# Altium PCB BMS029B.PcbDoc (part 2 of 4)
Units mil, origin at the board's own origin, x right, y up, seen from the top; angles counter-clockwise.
Board outline 4950 x 4000 mil, 4 copper layers (Layer 1 - Top Layer, Layer 2 - GND, Layer 3 - Signal, Layer 4 - Bottom Layer), stack 61.4 mil thick; 370 components, 202 nets, 969 pads, 408 vias.
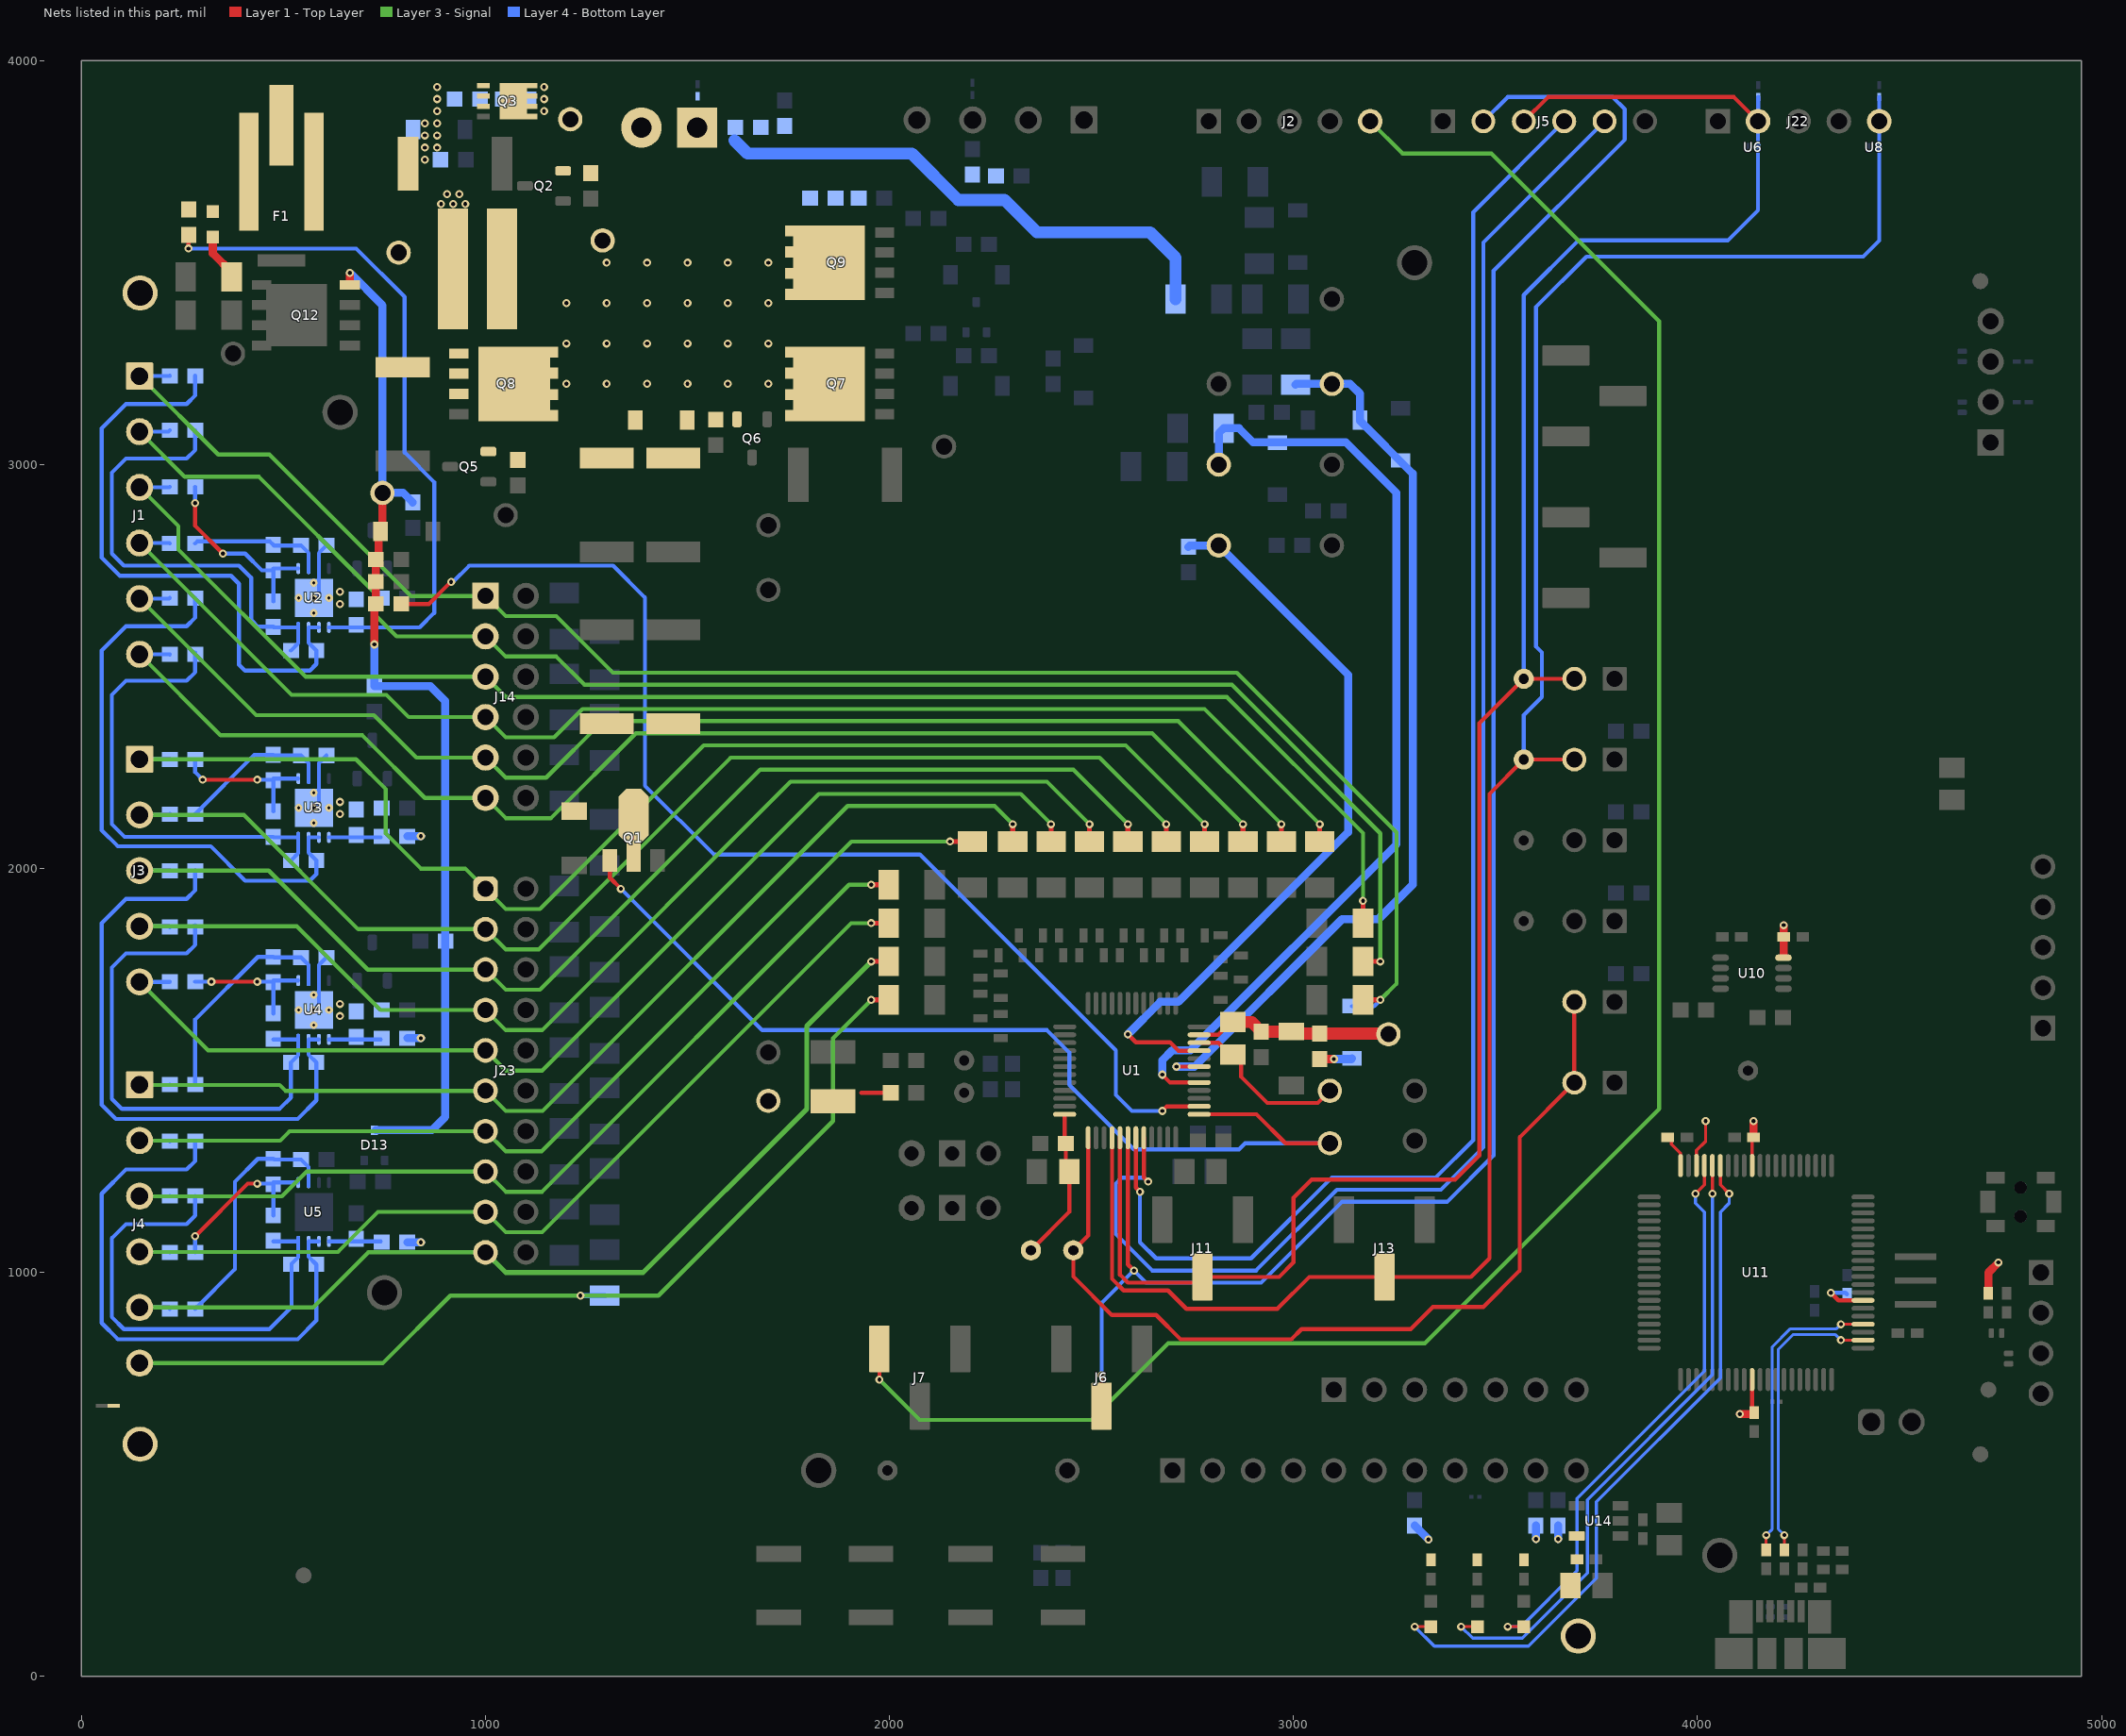
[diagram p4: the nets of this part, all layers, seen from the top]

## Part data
C1 C71: library part CMP-0008710-2, "CAP, CERM, 1 uF, 100 V, +/- 10%, X7R, 1206", Cap_Case=1206_180, Manufacturer=TDK, Supplier Part Number 1=445-4467-1-ND, TempCo=X7R, Tolerance_%=10%, Value1="0.004575 ohm", Value2=100V, ValueDisplayed=1uF
C2: library part CMP-0007130-4, "CAP, CERM, 100 pF, 100 V, +/- 5%, C0G/NP0, AEC-Q200 Grade 1, 0603", Cap_Case=0603, Manufacturer=MuRata, Supplier Part Number 1=490-4771-1-ND, TempCo=C0G/NP0, Tolerance_%=5%, Value1=Unknown, Value2=100V, ValueDisplayed=100pF
C3: library part CMP-0008010-2, "CAP, CERM, 0.47 uF, 25 V, +/- 10%, X7R, AEC-Q200 Grade 1, 0805", Cap_Case=0805, Manufacturer=MuRata, Supplier Part Number 1=490-8044-1-ND, TempCo=X7R, Tolerance_%=10%, Value1=Unknown, Value2=25V, ValueDisplayed=0.47uF
C4 C5 C6 C7 C8 C9 C10 C11 C14 C16 C17 C18 C19 C21 C22 C23 C24: library part CMP-0007047-4, "CAP, CERM, 0.22 uF, 50 V, +/- 10%, X7R, 0603", Cap_Case=0603, Manufacturer=TDK, Supplier Part Number 1=445-7408-1-ND, TempCo=X7R, Tolerance_%=10%, Value1="0.021699 ohm", Value2=50V, ValueDisplayed=0.22uF
C12 C15: library part CMP-0008000-2, "CAP, CERM, 1 uF, 16 V, +/- 10%, X7R, 0805", Cap_Case=0805, Manufacturer="Taiyo Yuden", Supplier Part Number 1=587-1283-1-ND, TempCo=X7R, Tolerance_%=10%, Value1=Unknown, Value2=16V, ValueDisplayed=1uF
C13: library part CMP-0006900-4, "CAP, CERM, 0.022 uF, 16 V, +/- 10%, X7R, 0603", Cap_Case=0603, Manufacturer=Kemet, Supplier Part Number 1=399-1093-1-ND, TempCo=X7R, Tolerance_%=10%, Value1=Unknown, Value2=16V, ValueDisplayed=0.022uF
C20 C26: library part CMP-0006828-4, "CAP, CERM, 0.01 uF, 16 V, +/- 10%, X7R, 0603", Cap_Case=0603, Manufacturer="Wurth Elektronik", Supplier Part Number 1=732-7959-1-ND, TempCo=X7R, Tolerance_%=10%, Value1=Unknown, Value2=16V, ValueDisplayed=0.01uF
C25: library part CMP-0008001-2, "CAP, CERM, 2.2 uF, 16 V, +/- 10%, X7R, 0805", Cap_Case=0805, Manufacturer="Taiyo Yuden", Supplier Part Number 1=587-1431-1-ND, TempCo=X7R, Tolerance_%=10%, Value1=Unknown, Value2=16V, ValueDisplayed=2.2uF
C27: library part CMP-0006841-4, "CAP, CERM, 100 pF, 50 V, +/- 5%, C0G/NP0, 0603", Cap_Case=0603, Manufacturer=Kemet, Supplier Part Number 1=399-1061-1-ND, TempCo=C0G/NP0, Tolerance_%=5%, Value1=Unknown, Value2=50V, ValueDisplayed=100pF
C28 C31 C32 C33 C35 C39 C40 C41 C43 C44 C46 C47 C48 C49 C50 C51 C52 C53 C54 C55 C56 C57: library part CMP-0006837-4, "CAP, CERM, 0.1 uF, 50 V, +/- 10%, X7R, 0603", Cap_Case=0603, Manufacturer="Wurth Elektronik", TempCo=X7R, Tolerance_%=10%, Value1=Unknown, Value2=50V, ValueDisplayed=0.1uF
C29 C30 C34 C36 C37 C38 C42 C45: library part CMP-0064935-4, "CAP, CERM, 0.1 uF, 100 V,+/- 10%, X7R, AEC-Q200 Grade 1, 0603", Cap_Case=0603, Manufacturer=MuRata, Supplier Part Number 1=490-13420-1-ND, TempCo=X7R, Tolerance_%=10%, Value1=Unknown, Value2=100V, ValueDisplayed=0.1uF
C58 C59 C60 C62 C65 C66 C68: library part CMP-0006228-2, "CAP, CERM, 0.1 uF, 16 V, +/- 10%, X7R, 0402", Cap_Case=0402, Manufacturer="Wurth Elektronik", Supplier Part Number 1=732-7532-1-ND, TempCo=X7R, Tolerance_%=10%, Value1=Unknown, Value2=16V, ValueDisplayed=0.1uF
C61 C67 C69: library part CMP-0006199-2, "CAP, CERM, 0.47 uF, 6.3 V, +/- 10%, X5R, 0402", Cap_Case=0402, Manufacturer=AVX, PartNumber=04026D474KAT2A, Supplier Part Number 1=478-6196-1-ND, TempCo=X5R, Tolerance_%=10%, Value1=Unknown, Value2=6.3V, ValueDisplayed=0.47uF
C63 C64: library part CMP-0085538-1, "CAP, CERM, 10 µF, 16 V,+/- 10%, X5R, 0805", Cap_Case=0805, Manufacturer="Samsung Electro-Mechanics", TempCo=X5R, Tolerance_%=10%, Value2=16V, ValueDisplayed=10µF
C70: library part CMP-0006224-2, "CAP, CERM, 2200 pF, 10 V, +/- 10%, X7R, 0402", Cap_Case=0402, Manufacturer="Wurth Elektronik", Supplier Part Number 1=732-7503-1-ND, TempCo=X7R, Tolerance_%=10%, Value1=Unknown, Value2=10V, ValueDisplayed=2200pF
D1 D2 D9 D10 D11 D12: library part CMP-0028450-2, "Diode, Schottky, 100 V, 0.15 A, SOD-123", Manufacturer="Diodes Inc.", Value1=0.15A, Value2=0.6V
D3: library part CMP-0002947-3, "LED, Red, SMD", Color=Red, Manufacturer="Wurth Elektronik", Power_TotalModule=72mW, Value1=0.072W, Value2=2V
D4 D5 D6: library part CMP-0005754-4, "Diode, Zener, 16 V, 500 mW, SOD-123", Manufacturer="Diodes Inc.", Power_W=500mW, Value1=0.5W
D7: library part CMP-0029001-2, "Diode, Ultrafast, 100 V, 0.15 A, SOD-123", Manufacturer="Diodes Inc.", Value1=0.15A, Value2=1.25V
D8: library part CMP-0005740-3, "Diode, Zener, 10 V, 500 mW, SOD-123", Manufacturer="ON Semiconductor", Power_W=500mW, Value1=0.5W
D13: library part CMP-0028438-2, "Diode, Schottky, 40 V, 0.2 A, SOT-323", Manufacturer="Diodes Inc.", Value1=0.2A, Value2=0.9V
D14 D15 D16: library part CMP-0002894-2, "LED, Green, SMD", Color=green, Manufacturer="Wurth Elektronik", Value1=W, Value2=2V
E1 E2 E3 E4 E5 E6: library part CMP-0079939-1
F1: library part CMP-0078325-2, "Fuse, 30 A, 62 VDC, SMD", Irating_A=30A, Manufacturer="Dexerials Corporation"
FID1 FID2 FID3 FID4 FID5 FID6: library part CMP-0077181-1, "Fiducial mark.  There is nothing to buy or mount.", Manufacturer=N/A
H1 H2 H3 H4: library part CMP-0003620-1, "Bumpon, Hemisphere, 0.44 X 0.20, Clear", Manufacturer=3M, Supplier Part Number 1=SJ5303-7-ND
J1 J4: library part CMP-0087050-1, "TERM BLOCK 3.5MM VERT 6POS PCB", Current_A=10A, Manufacturer="On Shore Technology", Voltage_V=300V
J2 J22 J28: library part CMP-0054597-1, "Header, 2.54mm, 5x1, Tin, TH", Color=Black, Current_A=3A, Manufacturer="Sullins Connector Solutions", Supplier Part Number 1=S1012E-05-ND, Voltage_V=1.8kV
J3: library part CMP-0087049-1, "TERM BLOCK 3.5MM VERT 5POS PCB", Current_A=10A, Manufacturer="On Shore Technology", Voltage_V=300V
J5: library part CMP-0054567-1, "Header, 100mil, 6x1, Tin, TH", Manufacturer="Sullins Connector Solutions", Supplier Part Number 1=S1012E-06-ND
J6 J7 J11 J13 J16 J19: library part CMP-0075388-1, "Header, 2.54mm, 3x1, Gold, SMT", Color=Black, Current_A=3A, Manufacturer=Molex, Supplier Part Number 1=0878980304-ND, Voltage_V=250V
J8: library part CMP-0074913-1, "Terminal Block, 3.5mm Pitch, 2x1, TH", Color=Grey, Current_A=6A, Manufacturer="On-Shore Technology", Supplier Part Number 1=ED1514-ND, Voltage_V=150V
J9: library part CMP-0087048-1, "TERM BLOCK 3.5MM VERT 4POS PCB", Current_A=10A, Manufacturer="On Shore Technology", Voltage_V=300V
J10 J12 J15 J18 J20 J21: library part CMP-0002337-1, "Header, 100mil, 2x1, Tin, TH", Color=Black, Current_A=3A, Manufacturer="Sullins Connector Solutions", Supplier Part Number 1=S1012E-02-ND, Voltage_V=1.8kV
J14: library part CMP-0054551-2, "Header, 100mil, 6x2, Tin, TH", Color=Black, Current_A=3A, Manufacturer="Sullins Connector Solutions", Supplier Part Number 1=S2012E-06-ND, Voltage_V=1.8kV
J17: library part CMP-0055187-1, "Header (friction lock), 100mil, 4x1, R/A, TH", Manufacturer=Molex, Supplier Part Number 1=WM4302-ND
J23: library part CMP-0054623-2, "Header, 2.54mm, 10x2, Tin, TH", Color=Black, Current_A=3A, Manufacturer="Sullins Connector Solutions", Supplier Part Number 1=S2012E-10-ND
J24: library part CMP-0054584-1, "Header, 2.54 mm, 7x1, Gold, TH", Color=Black, Current_A=3A, Manufacturer="Sullins Connector Solutions", Supplier Part Number 1=S1011E-07-ND, Voltage_V=1.8kV
J25: library part CMP-0054585-1, "Header, 2.54 mm, 11x1, Gold, TH", Color=Black, Current_A=3A, Manufacturer="Sullins Connector Solutions", Supplier Part Number 1=S1011E-11-ND, Voltage_V=1.8kV
J26: library part CMP-0055304-1, "Receptacle, Micro-USB Type B, 0.65 mm, 5x1, R/A, Bottom Mount SMT", Manufacturer=Molex, PartNumber=47346-1001, Supplier Part Number 1=06X9936
J27: library part CMP-0054794-2, "Header, 2.54 mm, 2x1, Gold, TH", Color=Black, Manufacturer="Wurth Elektronik", Supplier Part Number 1=732-5315-ND
J29: library part CMP-0055331-1, "Header, 2.54mm, 4x1, Tin, TH", Color=Black, Current_A=4A, Manufacturer=Molex, Supplier Part Number 1=WM50016-04-ND, Voltage_V=250V
LOGO4 LOGO5: library part CMP-0074835-1, "IEC 61010-1 High Voltage Warning"
Logo8: library part CMP-0074847-1, "FCC_disclaimer"
Logo9: library part CMP-0074769-1
Logo10: library part CMP-0074836-1, "IEC 61010-1 Caution Warning"
NT1 NT2 NT3 NT4 NT5: library part CMP-0078142-3, "Single point connection between nets.", Manufacturer=N/A
Q1: library part CMP-0000510-2, "Transistor, NPN, 150 V, 1 A, AEC-Q101, SOT-89", Manufacturer="Diodes Inc.", Supplier Part Number 1=FCX495CT-ND, Value1="1 A", Value2=300
Q2 Q5 Q6: library part CMP-0000093-3, "MOSFET, P-CH, -150 V, -0.53 A, SOT-23", Alternate Manufacturer=None, Manufacturer=Vishay-Siliconix, Value2="7.7 nC"
Q3: library part CMP-0001051-2, "MOSFET, N-CH, 150 V, 13 A, PG-TSDSON-8", Alternate Manufacturer=None, Manufacturer="Infineon Technologies", Supplier Part Number 1="BSZ900N15NS3 GCT-ND", Value2="5 nC"
Q4 Q11 Q13: library part CMP-0000333-2, "Transistor, PNP, 150 V, 0.5 A, SOT-23", Manufacturer="ON Semiconductor", Supplier Part Number 1=MMBT5401LT1GOSCT-ND, Value1="0.5 A", Value2=240
Q7 Q8 Q9: library part CMP-0067566-1, "MOSFET, N-CH, 150 V, 56 A, PG-TDSON-8", Alternate Manufacturer=None, Manufacturer="Infineon Technologies", Supplier Part Number 1=BSC160N15NS5ATMA1-ND, Value1="? ohm", Value2="19 nC"
Q10: library part CMP-0000774-1, "MOSFET, N-CH, 60 V, 0.31 A, SOT-323", Alternate Manufacturer=None, Manufacturer="Fairchild Semiconductor", PartNumber=2N7002KW, Supplier Part Number 1=2N7002KWCT-ND, Value1=1
Q12: library part CMP-0001069-3, "MOSFET, N-CH, 150 V, 3 A, PowerPAK SO-8", Alternate Manufacturer=None, Manufacturer=Vishay-Siliconix, Supplier Part Number 1=SI7898DP-T1-E3CT-ND, Value1=0.07, Value2="17 nC"
R1 R27 R28 R31 R41 R67 R81: library part CMP-0025700-4, "RES, 100, 5%, 0.1 W, AEC-Q200 Grade 0, 0603", Manufacturer=Vishay-Dale, PartNumber=CRCW0603100RJNEA, Power_W=100mW, Supplier Part Number 1=541-100GCT-ND, TempCo="200 ppm/C", Tolerance_%=5%, Value2=0.1W, Value_Code=100R, ValueDisplayed=100
R2 R3 R4 R7 R8 R11 R12 R13 R14 R16 R17 R18 R19 R21 R22 R23 R24: library part CMP-0016781-3, "RES, 20.0, 1%, 0.25 W, AEC-Q200 Grade 0, 1206", Manufacturer=Vishay-Dale, Power_W=250mW, Supplier Part Number 1=541-20.0FCT-ND, TempCo="100 ppm/C", Tolerance_%=1%, Value2=0.25W, Value_Code=20R0, ValueDisplayed=20.0
R5 R6 R9 R10: library part CMP-0015916-3, "RES, 220, 5%, 1 W, AEC-Q200 Grade 0, 2512", Manufacturer=Vishay-Dale, Power_W=1W, Supplier Part Number 1=541-220XCT-ND, TempCo="200 ppm/C", Tolerance_%=5%, Value_Code=220R, ValueDisplayed=220
R15 R56 R112 R113: library part CMP-0025697-4, "RES, 0, 5%, 0.1 W, AEC-Q200 Grade 0, 0603", Manufacturer=Vishay-Dale, Power_W=100mW, Supplier Part Number 1=541-0.0GCT-ND, TempCo="200 ppm/C", Tolerance_%=5%, Value2=0.1W, Value_Code=0000, ValueDisplayed=0
R20 R25 R29 R89 R92 R94 R97 R99 R109 R110 R111: library part CMP-0025701-4, "RES, 10 k, 5%, 0.1 W, AEC-Q200 Grade 0, 0603", Manufacturer=Vishay-Dale, Power_W=100mW, Supplier Part Number 1=541-10KGCT-ND, TempCo="200 ppm/C", Tolerance_%=5%, Value2=0.1W, Value_Code=10k0, ValueDisplayed=10k
R26 R91: library part CMP-0025698-4, "RES, 100 k, 5%, 0.1 W, AEC-Q200 Grade 0, 0603", Manufacturer=Vishay-Dale, Power_W=100mW, Supplier Part Number 1=541-100KGCT-ND, TempCo="200 ppm/C", Tolerance_%=5%, Value2=0.1W, Value_Code=100k
R30: library part CMP-0015200-2, "RES, 0.001, 1%, 1 W, 1210", Manufacturer=Rohm, PartNumber=PMR25HZPFV1L00, Power_W=1W, Supplier Part Number 1=RHM.001APCT-ND, TempCo="100 ppm/C", Tolerance_%=1%, Value_Code=1L000, ValueDisplayed=0.001
R32 R34 R36 R37 R47 R49 R53 R54 R69 R72 R75 R78 R83 R84 R85 R86: library part CMP-0025729-4, "RES, 1.0 k, 5%, 0.1 W, AEC-Q200 Grade 0, 0603", Manufacturer=Vishay-Dale, PartNumber=CRCW06031K00JNEA, Power_W=100mW, Supplier Part Number 1=541-1.0KGCT-ND, TempCo="200 ppm/C", Tolerance_%=5%, Value2=0.1W, Value_Code=1k00, ValueDisplayed=1.0k
R33 R39 R40: library part CMP-0015972-3, "RES, 4.7 k, 5%, 1 W, AEC-Q200 Grade 0, 2512", Manufacturer=Vishay-Dale, Power_W=1W, Supplier Part Number 1=541-4.7KXCT-ND, TempCo="200 ppm/C", Tolerance_%=5%, Value_Code=4k70, ValueDisplayed=4.7k
R35 R42 R43 R50 R51 R52: library part CMP-0025702-4, "RES, 10 M, 5%, 0.1 W, AEC-Q200 Grade 0, 0603", Manufacturer=Vishay-Dale, PartNumber=CRCW060310M0JNEA, Power_W=100mW, Supplier Part Number 1=541-10MGCT-ND, TempCo="200 ppm/C", Tolerance_%=5%, Value2=0.1W, Value_Code=10M0, ValueDisplayed=10M
R38 R58 R79: library part CMP-0025753-4, "RES, 20 k, 5%, 0.1 W, AEC-Q200 Grade 0, 0603", Manufacturer=Vishay-Dale, Power_W=100mW, Supplier Part Number 1=541-20KGCT-ND, TempCo="200 ppm/C", Tolerance_%=5%, Value2=0.1W, Value_Code=20k0, ValueDisplayed=20k
R44: library part CMP-0023326-5, "RES, 95.3 k, 1%, 0.1 W, 0603", Manufacturer=Yageo, Power_W=100mW, Supplier Part Number 1=311-95.3KHRCT-ND, TempCo="100 ppm/C", Tolerance_%=1%, Value2=0.1W, Value_Code=95k3, ValueDisplayed=95.3k
R45 R48: library part CMP-0018728-3, "RES, 7.5 k, 5%, 0.25 W, AEC-Q200 Grade 0, 1206", Manufacturer=Vishay-Dale, Power_W=250mW, Supplier Part Number 1=541-7.5KECT-ND, TempCo="200 ppm/C", Tolerance_%=5%, Value2=0.25W, Value_Code=7k50, ValueDisplayed=7.5k
R46: library part CMP-0015368-2, "RES, 0, 5%, 2 W, 2512 WIDE", Manufacturer="Vishay Draloric", PartNumber=RCL12250000Z0EG, Power_W=2W, Supplier Part Number 1=RCL0.0ECT-ND, TempCo=ppm/C, Tolerance_%=5%, Value_Code=0000, ValueDisplayed=0
R55: library part CMP-0025825-4, "RES, 51, 5%, 0.1 W, AEC-Q200 Grade 0, 0603", Manufacturer=Vishay-Dale, Power_W=100mW, Supplier Part Number 1=541-51GCT-ND, TempCo="200 ppm/C", Tolerance_%=5%, Value2=0.1W, Value_Code=51R0, ValueDisplayed=51
R57: library part CMP-0025701-4, "RES, 10 k, 5%, 0.1 W, AEC-Q200 Grade 0, 0603", Manufacturer=Vishay-Dale, PartNumber=CRCW060310K0JNEA, Power_W=100mW, Supplier Part Number 1=541-10KGCT-ND, TempCo="200 ppm/C", Tolerance_%=5%, Value2=0.1W, Value_Code=10k0, ValueDisplayed=10k
R59 R82: library part CMP-0025830-4, "RES, 5.1 k, 5%, 0.1 W, AEC-Q200 Grade 0, 0603", Manufacturer=Vishay-Dale, PartNumber=CRCW06035K10JNEA, Power_W=100mW, Supplier Part Number 1=541-5.1KGCT-ND, TempCo="200 ppm/C", Tolerance_%=5%, Value2=0.1W, Value_Code=5k10, ValueDisplayed=5.1k
R60: library part CMP-0025935-5, "RES, 62 k, 5%, 0.1 W, 0603", Manufacturer=Yageo, Power_W=100mW, Supplier Part Number 1=311-62KGRCT-ND, TempCo="100 ppm/C", Tolerance_%=5%, Value2=0.1W, Value_Code=62k0, ValueDisplayed=62k
R61 R62 R63: library part CMP-0025830-4, "RES, 5.1 k, 5%, 0.1 W, AEC-Q200 Grade 0, 0603", Manufacturer=Vishay-Dale, Power_W=100mW, Supplier Part Number 1=541-5.1KGCT-ND, TempCo="200 ppm/C", Tolerance_%=5%, Value2=0.1W, Value_Code=5k10, ValueDisplayed=5.1k
R64 R68 R70 R71 R73 R74 R76 R77: library part CMP-0018703-3, "RES, 5.1 k, 5%, 0.25 W, AEC-Q200 Grade 0, 1206", Manufacturer=Vishay-Dale, Power_W=250mW, Supplier Part Number 1=541-5.1KECT-ND, TempCo="200 ppm/C", Tolerance_%=5%, Value2=0.25W, Value_Code=5k10, ValueDisplayed=5.1k
R65: library part CMP-0025855-4, "RES, 7.5 k, 5%, 0.1 W, AEC-Q200 Grade 0, 0603", Manufacturer=Vishay-Dale, Power_W=100mW, Supplier Part Number 1=541-7.5KGCT-ND, TempCo="200 ppm/C", Tolerance_%=5%, Value2=0.1W, Value_Code=7k50, ValueDisplayed=7.5k
R66: library part CMP-0025753-4, "RES, 20 k, 5%, 0.1 W, AEC-Q200 Grade 0, 0603", Manufacturer=Vishay-Dale, PartNumber=CRCW060320K0JNEA, Power_W=100mW, Supplier Part Number 1=541-20KGCT-ND, TempCo="200 ppm/C", Tolerance_%=5%, Value2=0.1W, Value_Code=20k0, ValueDisplayed=20k
R80: library part CMP-0025766-4, "RES, 27 k, 5%, 0.1 W, AEC-Q200 Grade 0, 0603", Manufacturer=Vishay-Dale, Power_W=100mW, Supplier Part Number 1=541-27KGCT-ND, TempCo="200 ppm/C", Tolerance_%=5%, Value2=0.1W, Value_Code=27k0, ValueDisplayed=27k
R87 R88 R90 R93 R95 R96 R98 R100 R101 R102 R103 R104 R105 R106 R107 R108: library part CMP-0016776-3, "RES, 200, 1%, 0.25 W, AEC-Q200 Grade 0, 1206", Manufacturer=Vishay-Dale, Power_W=250mW, Supplier Part Number 1=541-200FCT-ND, TempCo="100 ppm/C", Tolerance_%=1%, Value2=0.25W, Value_Code=200R, ValueDisplayed=200
R114 R115: library part CMP-0026908-3, "RES, 33, 5%, 0.063 W, AEC-Q200 Grade 0, 0402", Manufacturer=Vishay-Dale, PartNumber=CRCW040233R0JNED, Power_W=63mW, Supplier Part Number 1=541-33JCT-ND, TempCo="200 ppm/C", Tolerance_%=5%, Value2=0.063W, Value_Code=33R0, ValueDisplayed=33
R116: library part CMP-0026889-5, "RES, 2.0 k, 5%, 0.063 W, AEC-Q200 Grade 0, 0402", Manufacturer=Vishay-Dale, PartNumber=CRCW04022K00JNED, Power_W=63mW, Supplier Part Number 1=541-2.0KJCT-ND, TempCo="200 ppm/C", Tolerance_%=5%, Value2=0.063W, Value_Code=2k00, ValueDisplayed=2.0k
R117 R123: library part CMP-0026825-5, "RES, 10 k, 5%, 0.063 W, AEC-Q200 Grade 0, 0402", Manufacturer=Vishay-Dale, PartNumber=CRCW040210K0JNED, Power_W=63mW, Supplier Part Number 1=541-10KJCT-ND, TempCo="200 ppm/C", Tolerance_%=5%, Value2=0.063W, Value_Code=10k0, ValueDisplayed=10k
R118 R119: library part CMP-0026859-2, "RES, 1.0 M, 5%, 0.063 W, AEC-Q200 Grade 0, 0402", Manufacturer=Vishay-Dale, PartNumber=CRCW04021M00JNED, Power_W=63mW, Supplier Part Number 1=541-1.0MJCT-ND, TempCo="200 ppm/C", Tolerance_%=5%, Value2=0.063W, Value_Code=1M00, ValueDisplayed=1.0M
R120 R121 R122: library part CMP-0026694-1, "RES, 330, 1%, 0.1 W, AEC-Q200 Grade 0, 0402", Manufacturer=Panasonic, PartNumber=ERJ-2RKF3300X, Power_W=100mW, Supplier Part Number 1=P330LCT-ND, TempCo="100 ppm/C", Tolerance_%=1%, Value2=0.1W, Value_Code=330R, ValueDisplayed=330
RT1 RT2: library part CMP-0002341-2, "Thermistor NTC, 10.0k ohm, 1%, Disc, 5x8.4 mm", Manufacturer="SEMITEC Corporation", PartNumber=103AT-2, Power_W=10mW, Supplier Part Number 1=954-103AT-2, Tolerance_%=1%
S1 S2: library part CMP-0002132-2, "Switch, Tactile, SPST-NO, SMT", CurrentRating_mA=50A, Manufacturer="C&K Components", PartNumber=KST221JLFS, Supplier Part Number 1=401-1848-1-ND
S3: library part CMP-0002246-2, "Switch, SPST-NO,  Off-Mom, 0.05A, 12VDC, SMD", CurrentRating_mA=50A, Manufacturer="C&K Components", Supplier Part Number 1=CKN10505CT-ND
SH-J1 SH-J2 SH-J3 SH-J4 SH-J5 SH-J6 SH-J7 SH-J8 SH-J9 SH-J10 SH-J11 SH-J12 SH-J13 SH-J14 SH-J15 SH-J16 SH-J17 SH-J18 SH-J19 SH-J20 SH-J21: library part CMP-0003623-3, "Shunt, 100mil, Gold plated, Black", Alternate Manufacturer=3M, Alternate PartNumber=969102-0000-DA, Manufacturer=Samtec, Supplier Part Number 1=SAM8858-ND
TP1: library part CMP-0055147-1, "Test Point, Multipurpose, Red, TH", Color=Red, Manufacturer=Keystone, PartNumber=5010, Supplier Part Number 1=36-5010-ND
TP2 TP3 TP4 TP5 TP6 TP7 TP8 TP10 TP11 TP12 TP13 TP18 TP19 TP20 TP21 TP22 TP23 TP24 TP25 TP26 TP27 TP28 TP29 TP30 TP31 TP32 TP33 TP34 TP35 TP36 TP37 TP38 TP39 TP40 TP41 TP42: library part CMP-0078143-2, "TEST POINT.  No entry in BOM.", Manufacturer=N/A
TP9: library part CMP-0055148-1, "Test Point, Multipurpose, Black, TH", Color=Black, Manufacturer=Keystone, PartNumber=5011, Supplier Part Number 1=36-5011-ND
TP14 TP15 TP16 TP17: library part CMP-0055143-1, "Test Point, Compact, Black, TH", Color=Black, Manufacturer=Keystone, Supplier Part Number 1=36-5006-ND
TP43 TP44: library part CMP-0055142-1, "Test Point, Compact, Red, TH", Color=Red, Manufacturer=Keystone, Supplier Part Number 1=36-5005-ND
TP45: library part CMP-0003825-1, "1mm Test Point, SMT", Manufacturer=Any, PartNumber=TP_SM_1MM
U1: library part CMP-0084229-1, "Multicell Battery Monitor and Protection Family, PFB0048A (TQFP-48)", Alternate Manufacturer="Texas Instruments", Alternate PartNumber=bq76952PFBR
U2 U3 U4 U5: library part CMP-0078902-2, "Family 2-5S Overvoltage Protector with Internal Delay Timer, DPJ0008A (WSON-8)", Alternate Manufacturer="Texas Instruments", Alternate PartNumber=BQ771807DPJT
U6 U7 U8 U9: library part CMP-0043093-3, "Single-Channel ESD in 0402 Package With 10pF Capacitance and 6V Breakdown, DPY0002A (X1SON-2)", Alternate Manufacturer="Texas Instruments", Alternate PartNumber=TPD1E10B06DPYT, Breakdown Voltage(Min)(V)=6, IO Capacitance(Typ)(pF)=10, Operating Temperature Range="-40 to 125 C", Rating=Catalog
U10: library part CMP-0051048-2, "Dual-Bit Dual Supply Transceiver with Configurable Voltage Translation and 3-State Outputs, DCT0008A, LARGE T&R", F @ Nom Voltage(Max)(Mhz)=150, Generic Part Number=SN74LVC2T45, ICC @ Nom Voltage(Max)(mA)=0.004, Manufacturer="Texas Instruments", Operating Temperature Range(C)="-40 to 85", Rating=Military, tpd @ Nom Voltage(Max)(ns)=17.7,10.3,8.3,7.2, Voltage(Nom)(V)=1.8,2.5,3.3,5
U11: "25 MHz Mixed Signal Microcontroller with 128 KB Flash, 8192 B SRAM and 63 GPIOs, -40 to 85 degC, 80-pin QFP (PN), Green (RoHS & no Sb/Br)", Frequency(MHz)=25, Manufacturer="Texas Instruments", PartNumber=MSP430F5529IPN, Temp Sensor=Yes
U12 U13 U15 U16: library part CMP-0043094-3, "Single-Channel ESD in 0402 Package With 10pF Capacitance and 6V Breakdown, DPY0002A (X1SON-2)", Alternate Manufacturer="Texas Instruments", Alternate PartNumber=TPD1E10B06DPYR, Breakdown Voltage(Min)(V)=6, IO Capacitance(Typ)(pF)=10, Operating Temperature Range="-40 to 125 C", Rating=Catalog
U14: "Single Output LDO, 150 mA, Fixed 3.3 V Output, 2.7 to 10 V Input, with Low IQ, 5-pin SOT-23 (DBV), -40 to 125 degC, Green (RoHS & no Sb/Br)", Manufacturer="Texas Instruments", PartNumber=TPS76333DBVR
Y1: library part CMP-0084387-1, "Resonator, 4 MHz, 39 pF, AEC-Q200 Grade 1, SMD", Frequency_Fixed=4MHz, Load Capacitance="39 pF", Manufacturer=MuRata
ZZ1: library part CMP-0077236-1
ZZ2: library part CMP-0077237-1
ZZ3: library part CMP-0077238-1

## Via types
v1: diameter 20, hole 10, Layer 1 - Top Layer to Layer 4 - Bottom Layer, tented both sides, 376 vias
v2: diameter 19.68, hole 7.87, Layer 1 - Top Layer to Layer 4 - Bottom Layer, tented both sides, 32 vias

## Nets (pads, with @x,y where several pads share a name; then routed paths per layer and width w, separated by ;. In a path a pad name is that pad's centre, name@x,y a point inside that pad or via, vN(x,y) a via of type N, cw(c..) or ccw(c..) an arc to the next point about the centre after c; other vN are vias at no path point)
1P: J4.5 J23.19 R23.1 R86.1 | length 2446.3
  Layer 1 - Top Layer w12: v1(1955,1770) R23.1@1997.91,1770
  Layer 3 - Signal w10: J4.5@143.94,913.31 573.31,913.31 710,1050 J23.19@1000,1050
  Layer 3 - Signal w12: J23.19@1000,1050 1050,1000 1390,1000 1795,1405 1795,1610 v1(1955,1770)
  Layer 4 - Bottom Layer w10: J4.5@143.94,913.31 215.2,913.31 R86.1@218.5,910
2P: J4.4 J23.17 R22.1 R85.1 | length 2307.5
  Layer 1 - Top Layer w12: v1(1955,1865) R22.1@1997.91,1865
  Layer 3 - Signal w10: J4.4@143.94,1051.1 634.8,1051.1 733.7,1150 J23.17@1000,1150 1050,1100 1140,1100 1905,1865 v1(1955,1865)
  Layer 4 - Bottom Layer w10: J4.4@143.94,1051.1 217.4,1051.1 R85.1@218.5,1050
3.3V: C59.2 C64.1 C65.1 C68.1 C69.1 R109.1 R110.1 R111.1 R120.2 R121.2 R122.2 R123.2 TP44.1 U10.8 U11.11 U11.18 U11.50 U14.5 | length 630.6
  Layer 1 - Top Layer w8: U11.18@3997.36,1264.76 3997.36,1302.36 4020,1325 v1(4020,1375) ; U11.11@4135.16,1264.76 4135.16,1331.54 C69.1@4138.62,1335
  Layer 1 - Top Layer w10: U11.50@4135.16,735.24 4135.16,658.46 C68.1@4140,653.62
  Layer 1 - Top Layer w20: v1(4105,650) 4136.38,650 C68.1@4140,653.62 ; C69.1@4138.62,1335 v1(4138.62,1375) ; U10.8@4213.38,1783 C59.2@4213.38,1831 v1(4213.38,1860) ; R123.2@4720,948.62 4720,1000 v1(4745,1025)
  Layer 4 - Bottom Layer w20: R111.1@3300,373.5 v1(3334.25,339.25) ; v1(3600,340) R110.1@3600,373.5 ; v1(3655,340) R109.1@3655,373.5
3P: J4.3 J23.15 R21.1 R84.1 | length 2289.8
  Layer 1 - Top Layer w12: v1(1955,1960) R21.1@1997.91,1960
  Layer 3 - Signal w10: J4.3@143.94,1188.9 496.06,1188.9 557.17,1250 J23.15@1000,1250 1050,1200 1140,1200 1900,1960 v1(1955,1960)
  Layer 4 - Bottom Layer w10: J4.3@143.94,1188.9 217.4,1188.9 R84.1@218.5,1190
4P: C49.1 C52.1 J4.2 J23.13 R19.1 R79.1 R81.1 R83.1 U4.7 U4.9 | length 2661
  Layer 1 - Top Layer w12: v1(2150,2067.09) R19.1@2205,2067.09
  Layer 3 - Signal w10: J4.2@143.94,1326.69 491.69,1326.69 515,1350 J23.13@1000,1350 1050,1300 1138.74,1300 1905.83,2067.09 v1(2150,2067.09)
  Layer 4 - Bottom Layer w10: J4.2@143.94,1326.69 216.81,1326.69 R83.1@218.5,1325 ; v2(575,1650) 587.8,1662.8 U4.7@587.8,1722.83 587.8,1761.3 C52.1@606.5,1780
  Layer 4 - Bottom Layer w20: R81.1@806.5,1075 v1(840,1075)
  other v1: 640,1635 640,1665
  other v2: 575,1612.6 537.6,1650 612.4,1650 575,1687.4
5P: J4.1 J23.11 R18.1 R78.1 | length 2636.8
  Layer 1 - Top Layer w12: R18.1@2305,2067.09 v1(2305,2110)
  Layer 3 - Signal w10: J4.1@143.94,1464.49 490.51,1464.49 505,1450 J23.11@1000,1450 1050,1400 1141.26,1400 1896.26,2155 2260,2155 v1(2305,2110)
  Layer 4 - Bottom Layer w10: J4.1@143.94,1464.49 217.99,1464.49 R78.1@218.5,1465
6P: J3.5 J23.9 R17.1 R75.1 | length 2779.5
  Layer 1 - Top Layer w12: R17.1@2400,2067.09 v1(2400,2110)
  Layer 3 - Signal w10: J3.5@143.94,1719.41 313.35,1550 J23.9@1000,1550 1050,1500 1140,1500 1825,2185 2325,2185 v1(2400,2110)
  Layer 4 - Bottom Layer w10: J3.5@143.94,1719.41 217.91,1719.41 R75.1@218.5,1720
7P: J3.4 J23.7 R16.1 R72.1 | length 2874.2
  Layer 1 - Top Layer w12: R16.1@2495,2067.09 v1(2495,2110)
  Layer 3 - Signal w10: J3.4@143.94,1857.2 532.8,1857.2 740,1650 J23.7@1000,1650 1050,1600 1140,1600 1755,2215 2390,2215 v1(2495,2110)
  Layer 4 - Bottom Layer w10: J3.4@143.94,1857.2 216.3,1857.2 R72.1@218.5,1855
8P: C41.1 C46.1 J3.3 J23.5 R14.1 R58.1 R67.1 R69.1 U3.7 U3.9 | length 3144
  Layer 1 - Top Layer w12: R14.1@2590,2067.09 v1(2590,2110)
  Layer 3 - Signal w10: J3.3@143.94,1995 463.5,1995 708.5,1750 J23.5@1000,1750 1050,1700 1135,1700 1680,2245 2455,2245 v1(2590,2110)
  Layer 4 - Bottom Layer w10: J3.3@143.94,1995 R69.1@218.5,1995 ; v2(575,2150) 587.8,2162.8 U3.7@587.8,2222.83 587.8,2261.3 C46.1@606.5,2280
  Layer 4 - Bottom Layer w20: R67.1@806.5,1580 v1(840,1580)
  other v1: 640,2135 640,2165
  other v2: 575,2112.6 537.6,2150 612.4,2150 575,2187.4
9P: J3.2 J23.3 R13.1 R54.1 | length 3062.4
  Layer 1 - Top Layer w12: R13.1@2685,2067.09 v1(2685,2110)
  Layer 3 - Signal w10: J3.2@143.94,2132.8 402.2,2132.8 685,1850 J23.3@1000,1850 1050,1800 1131.93,1800 1606.93,2275 2520,2275 v1(2685,2110)
  Layer 4 - Bottom Layer w10: J3.2@143.94,2132.8 216.3,2132.8 R54.1@218.5,2135
10P: J3.1 J23.1 R12.1 R53.1 | length 3220.3
  Layer 1 - Top Layer w12: R12.1@2780,2067.09 v1(2780,2110)
  Layer 3 - Signal w10: J3.1@143.94,2270.59 679.41,2270.59 753.33,2196.67 753.33,2086.67 840,2000 950,2000 J23.1@1000,1950 1050,1900 1135,1900 1540,2305 2585,2305 v1(2780,2110)
  Layer 4 - Bottom Layer w10: J3.1@143.94,2270.59 217.91,2270.59 R53.1@218.5,2270
11P: J1.6 J14.11 R11.1 R49.1 | length 3196.9
  Layer 1 - Top Layer w12: R11.1@2875,2067.09 v1(2875,2110)
  Layer 3 - Signal w10: J1.6@143.94,2530.51 344.45,2330 695,2330 850,2175 J14.11@1000,2175 1050,2125 1162.09,2125 1372.09,2335 2650,2335 v1(2875,2110)
  Layer 4 - Bottom Layer w10: J1.6@143.94,2530.51 217.99,2530.51 R49.1@218.5,2530
12P: C32.1 C39.1 J1.5 J14.9 R8.1 R38.1 R41.1 R47.1 U2.7 U2.9 | length 3468
  Layer 1 - Top Layer w12: R8.1@2970,2067.09 v1(2970,2110)
  Layer 3 - Signal w10: J1.5@143.94,2668.31 432.24,2380 723.9,2380 828.9,2275 J14.9@1000,2275 1050,2225 1150,2225 1290,2365 2715,2365 v1(2970,2110)
  Layer 4 - Bottom Layer w10: J1.5@143.94,2668.31 216.81,2668.31 R47.1@218.5,2670 ; v2(575,2670) 587.8,2682.8 U2.7@587.8,2742.83 587.8,2781.3 C39.1@606.5,2800
  Layer 4 - Bottom Layer w20: R41.1@806.5,2080 v1(840,2080)
  other v1: 640,2655 640,2685
  other v2: 575,2632.6 537.6,2670 612.4,2670 575,2707.4
13P: J1.4 J14.7 R7.1 R37.1 | length 3385.3
  Layer 1 - Top Layer w12: R7.1@3065,2067.09 v1(3065,2110)
  Layer 3 - Signal w10: J1.4@143.94,2806.1 520.04,2430 755,2430 810,2375 J14.7@1000,2375 1050,2325 1170,2325 1240,2395 2780,2395 v1(3065,2110)
  Layer 4 - Bottom Layer w10: J1.4@143.94,2806.1 217.4,2806.1 R37.1@218.5,2805
14P: J1.3 J14.5 R4.1 R36.1 | length 3714.5
  Layer 1 - Top Layer w12: R4.1@3172.09,1865 v1(3172.09,1920)
  Layer 3 - Signal w10: J1.3@143.94,2943.9 240,2847.83 240,2790 555,2475 J14.5@1000,2475 1050,2425 2835,2425 3172.09,2087.91 v1(3172.09,1920)
  Layer 4 - Bottom Layer w10: J1.3@143.94,2943.9 217.4,2943.9 R36.1@218.5,2945
15P: J1.2 J14.3 R3.1 R34.1 | length 3950.9
  Layer 1 - Top Layer w12: R3.1@3172.09,1770 v1(3215,1770)
  Layer 3 - Signal w10: J1.2@143.94,3081.69 255.63,2970 439.21,2970 728.5,2680.71 728.5,2626.5 780,2575 J14.3@1000,2575 1050,2525 1175,2525 1245,2455 2847.43,2455 3215,2087.43 v1(3215,1770)
  Layer 4 - Bottom Layer w10: J1.2@143.94,3081.69 215.2,3081.69 R34.1@218.5,3085
16P: D1.2 D3.2 F1.1 J1.1 J14.1 NT2.2 R2.1 R31.1 R32.1 TP1.1 | length 4204.5
  Layer 1 - Top Layer w12: R2.1@3172.09,1675 v1(3215,1675)
  Layer 3 - Signal w10: J1.1@143.94,3219.49 338.43,3025 465,3025 815,2675 J14.1@1000,2675 1050,2625 1175.32,2625 1315.32,2485 2859.85,2485 3255,2089.85 3255,1715 v1(3215,1675)
  Layer 4 - Bottom Layer w10: J1.1@143.94,3219.49 217.99,3219.49 R32.1@218.5,3220 ; D1.2@3145,1659.47 3199.47,1659.47 v1(3215,1675)
ALERT: J20.2 J21.2 TP41.1 U1.25 | length 2319.4
  Layer 1 - Top Layer w10: U1.25@2491.73,1333.66 2491.73,1091.73 TP41.1@2455,1055 2455,990 2550,895 2660,895 2720,835 2995,835 3020,860 3290,860 3345,915 3470,915 3560,1005 3560,1335 J21.2@3695,1470 J20.2@3695,1670
BAT-: J4.6 NT1.2 R24.1 R27.1 R30.2 R108.1 TP9.1 TP19.1 | length 2480.1
  Layer 1 - Top Layer w10: 1930,1445 R27.1@2003.5,1445
  Layer 1 - Top Layer w12: v1(1955,1675) R24.1@1997.91,1675
  Layer 3 - Signal w10: J4.6@143.94,775.51 745.51,775.51 912.91,942.91 v1(1235,942.91) 1427.91,942.91 1860,1375 1860,1580 v1(1955,1675)
  Layer 4 - Bottom Layer w12: v1(1235,942.91) R108.1@1295,942.91
BREG: Q1.1 TP4.1 U1.37 | length 2510.2
  Layer 1 - Top Layer w10: Q1.1@1307.6,2020.2 1307.6,1977.4 v1(1335,1950) ; U1.37@2766.34,1391.73 2908.27,1391.73 2980,1320 TP4.1@3090,1320
  Layer 4 - Bottom Layer w10: v1(1335,1950) 1685,1600 2390,1600 2445,1545 2445,1465 2605,1305 2865,1305 2880,1320 TP4.1@3090,1320
CD: D2.2 Q5.2 Q6.2 Q7.5 Q7.6 Q7.7 Q7.8 Q7.9 Q8.5 Q8.6 Q8.7 Q8.8 Q8.9 Q9.5 Q9.6 Q9.7 Q9.8 Q9.9 R42.1 R43.1 R46.2 TP23.1
  other v1: 1200,3200 1300,3200 1400,3200 1500,3200 1600,3200 1700,3200 1200,3300 1300,3300 1400,3300 1500,3300 1600,3300 1700,3300 1200,3400 1300,3400 1400,3400 1500,3400 1600,3400 1700,3400 1300,3500 1400,3500 1500,3500 1600,3500 1700,3500
CFETOFF: E3.1 J5.3 J10.2 J11.2 J22.2 TP37.1 U1.29 U6.1 | length 5338.2
  Layer 1 - Top Layer w10: U1.29@2570.47,1333.66 2570.47,994.53 2590,975 2760.87,975 J11.2@2775,989.14 2964.14,989.14 3000,1025 3000,1185 3045,1230 3400,1230 3460,1290 3460,2360 TP37.1@3570,2470 J10.2@3695,2470 ; J5.3@3570,3850 3630,3910 4090,3910 J22.2@4150,3850
  Layer 4 - Bottom Layer w10: TP37.1@3570,2470 3570,3420 3705,3555 4075,3555 4149.8,3629.8 U6.1@4149.8,3785 4149.8,3849.8 J22.2@4150,3850 E3.1@4150,3910
CHG: R61.1 TP30.1 U1.45 | length 1864.3
  Layer 1 - Top Layer w10: v1(2590,1590) 2610,1570 2694.21,1570 2715,1549.21 U1.45@2766.34,1549.21
  Layer 4 - Bottom Layer w20: v1(2590,1590) 2670,1670 2715,1670 3135,2090 3135,2480 TP30.1@2815,2800 2743.5,2800 R61.1@2740,2796.5
CPACK+: C30.1 C34.1 E1.1 J8.1 J8.2 Q2.2 Q3.5 Q3.6 Q3.7 Q3.8 Q3.9 R35.1 R71.1 TP20.1 | length 2629
  Layer 4 - Bottom Layer w30: 1649,3770 1616,3803 1649,3770 ; 1649,3770 2055,3770 ; 1649,3770 2055,3770 ; 2055,3770 2170,3655 ; 2055,3770 2170,3655 ; 2170,3655 2285,3655 ; 2170,3655 2285,3655 ; 2285,3655 2365,3575 ; 2285,3655 2365,3575 ; 2365,3575 2645,3575 ; 2365,3575 2645,3575 ; 2645,3575 2707.91,3512.09 ; 2645,3575 2707.91,3512.09 ; 2707.91,3512.09 R71.1@2707.91,3410 2707.91,3512.09
  other v1: 1145,3875 1145,3905 1145,3935
DCHG: J5.4 U1.31 | length 3841.2
  Layer 1 - Top Layer w10: U1.31@2609.84,1333.66 2609.84,1210.16 v1(2620,1200)
  Layer 4 - Bottom Layer w10: v1(2620,1200) 2620,1075 2660,1035 2895,1035 3095,1235 3352.43,1235 3445,1327.57 3445,3625 J5.4@3670,3850
DDSG: J5.5 U1.32 | length 4066
  Layer 1 - Top Layer w10: U1.32@2629.53,1333.66 2629.53,1235.47 v1(2640,1225)
  Layer 4 - Bottom Layer w10: v1(2640,1225) 2630,1235 2575,1235 2560,1220 2560,1095.28 2650.28,1005 2907.43,1005 3107.43,1205 3364.85,1205 3470,1310.15 3470,3550 J5.5@3770,3850
DFETOFF: J5.2 J6.2 U1.30 | length 4848.6
  Layer 1 - Top Layer w10: J6.2@2525,669.14 v1(2525,745) ; U1.30@2590.16,1333.66 2590.16,1019.84 v1(2605,1005)
  Layer 4 - Bottom Layer w10: v1(2525,745) 2525,925 v1(2605,1005) 2635,975 2920,975 3120,1175 3380,1175 3495,1290 3495,3480 3820,3805 3820,3880 3790,3910 3530,3910 J5.2@3470,3850
DM: R114.2 U11.64 | length 756.7
  Layer 1 - Top Layer w7: R114.2@4170,313.62 v1(4170,350) ; v1(4355,872.05) U11.64@4409.76,872.05
  Layer 4 - Bottom Layer w7: v1(4170,350) 4185,365 4185,816.21 4229.79,861 4343.95,861 v1(4355,872.05)
DP: R115.2 U11.62 | length 732.8
  Layer 1 - Top Layer w7: R115.2@4215,313.62 v1(4215,350) ; v1(4355,832.68) U11.62@4409.76,832.68
  Layer 4 - Bottom Layer w7: v1(4215,350) 4200,365 4200,810 4236,846 4341.68,846 v1(4355,832.68)
DSG: D9.1 D10.1 R68.1 TP35.1 U1.43 | length 2267.9
  Layer 1 - Top Layer w10: v1(2710,1509.84) U1.43@2766.34,1509.84
  Layer 4 - Bottom Layer w20: v1(2710,1509.84) 2755,1509.84 3120.16,1875 3210,1875 3295,1960 3295,2978 3164.47,3108.53 3164.47,3175.53 3140,3200 TP35.1@3095,3200 3007.09,3200 R68.1@3005,3197.91
EXTTS2: J2.5 J7.1 | length 5236.3
  Layer 1 - Top Layer w10: v1(1975.01,735.01) J7.1@1975,810.87
  Layer 3 - Signal w10: v1(1975.01,735.01) 2075.02,635 2500,635 2690,825 3325,825 3905,1405 3905,3355 3490,3770 3270,3770 J2.5@3190,3850
FBAT: C29.2 C37.2 D4.2 F1.3 NT2.1 Q3.1 Q3.2 Q3.3 Q8.1 Q8.2 Q8.3 R33.1 R39.1 R46.1 R50.1 TP21.1
  other v1: 890,3645 920,3645 950,3645 905,3670 935,3670 850,3755 850,3785 880,3785 850,3815 880,3815 850,3845 880,3845 880,3875 880,3905 880,3935
FUSE: R59.2 U1.38 | length 2915.5
  Layer 1 - Top Layer w10: R59.2@791.5,2655 860,2655 v1(915,2710) ; v1(2675,1400) 2686.42,1411.42 U1.38@2766.34,1411.42
  Layer 4 - Bottom Layer w10: v1(915,2710) 920,2710 960,2750 1315.94,2750 1395,2670.94 1395,2205 1565,2035 2075,2035 2560,1550 2560,1440 2600,1400 v1(2675,1400)
HDQ: E5.1 J12.2 J13.2 J22.5 TP38.1 U1.28 U8.1 | length 5179.6
  Layer 1 - Top Layer w10: U1.28@2550.79,1333.66 2550.79,984.21 2579.49,955.51 2689.49,955.51 2735,910 2960,910 3039.13,989.13 J13.2@3225,989.13 3439.13,989.13 3485,1035 3485,2185 TP38.1@3570,2270 J12.2@3695,2270
  Layer 4 - Bottom Layer w10: TP38.1@3570,2270 3570,2380 3615,2425 3615,2535 3600,2550 3600,3390 3725,3515 4410,3515 4449.8,3554.8 U8.1@4449.8,3785 4449.8,3849.8 J22.5@4450,3850 E5.1@4450,3910
LD: D12.1 R76.2 TP34.1 U1.41 | length 2395.2
  Layer 1 - Top Layer w10: v1(2675,1490) 2694.53,1470.47 U1.41@2766.34,1470.47
  Layer 4 - Bottom Layer w20: v1(2675,1490) 2675,1525 2700,1550 2745,1550 3255,2060 3255,2930 3130,3055 2900,3055 2865,3090 R76.2@2827.09,3090 2815,3077.91 TP34.1@2815,3000
LED1: D14.1 U11.15 | length 1746.4
  Layer 1 - Top Layer w8: v1(3300,123.5) D14.1@3340,123.5 ; U11.15@4056.42,1264.76 4056.42,1217.05 v1(4078.46,1195)
  Layer 4 - Bottom Layer w8: v1(3300,123.5) 3348.5,75 3581.56,75 3750,243.44 3750,432 4057,739 4057,1150 4078.46,1171.46 v1(4078.46,1195)
LED2: D15.1 U11.16 | length 1568
  Layer 1 - Top Layer w8: v1(3415,123.5) D15.1@3455,123.5 ; v1(4036.73,1195) U11.16@4036.73,1264.76
  Layer 4 - Bottom Layer w8: v1(3415,123.5) 3443.5,95 3566.56,95 3727.28,255.73 3727.28,437.57 4037,747.28 v1@4037,1195
LED3: D16.1 U11.17 | length 1420.9
  Layer 1 - Top Layer w8: v1(3530,123.5) D16.1@3570,123.5 ; v1(3995,1195) 4017.05,1217.05 U11.17@4017.05,1264.76
  Layer 4 - Bottom Layer w8: v1(3530,123.5) 3563.5,123.5 3702.28,262.28 3702.28,440.85 4017,755.57 4017,1150 3995,1172 v1(3995,1195)
NetC1_1: C1.1 C2.1 C3.1 R1.1 TP2.1 U1.47 | length 494.5
  Layer 1 - Top Layer w10: U1.47@2766.34,1588.58 2813.58,1588.58 2845,1620 C3.1@2850,1620
  Layer 1 - Top Layer w30: C3.1@2850,1620 2896.5,1620 C2.1@2920,1596.5 2994.57,1596.5 C1.1@2995,1596.93 3000.43,1591.5 R1.1@3065,1591.5 3233.5,1591.5 TP2.1@3235,1590
NetC3_2: C3.2 TP3.1 U1.46 | length 418.3
  Layer 1 - Top Layer w10: U1.46@2766.34,1568.9 2814.1,1568.9 2843,1540 C3.2@2850,1540 2870,1520 2870,1485 2935,1420 3060,1420 TP3.1@3090,1450
NetC25_2: C25.2 C26.1 TP10.1 U1.24 | length 380.8
  Layer 1 - Top Layer w10: TP10.1@2350,1055 2445,1150 C25.2@2445,1250 2436.5,1258.5 C26.1@2436.5,1320 2433.66,1322.83 U1.24@2433.66,1391.73
NetC29_1: C29.1 C30.2
NetC31_1: C31.1 C33.2 R34.2 U2.4 | length 1150.2
  Layer 4 - Bottom Layer w10: R34.2@281.5,3085 281.5,3036.5 260,3015 110,3015 75,2980 75,2780 105,2750 390,2750 420,2720 420,2615 436.5,2598.5 C33.2@475,2598.5 ; C33.2@475,2597.17 U2.4@536.61,2597.17 ; C31.1@518.5,2540 536.61,2558.11 U2.4@536.61,2597.17 ; U2.4@536.61,2606 U2.4@536.61,2597.17
NetC31_2: C31.2 R32.2 U2.2 U2.3 | length 1527.9
  Layer 4 - Bottom Layer w10: R32.2@281.5,3220 281.5,3171.5 260,3150 110,3150 50,3090 50,2770 95,2725 370,2725 390,2705 390,2505 405,2490 565,2490 581.5,2506.5 C31.2@581.5,2540 562.2,2559.29 U2.3@562.2,2597.17 ; U2.3@563,2597.17 U2.2@587,2597.17
NetC32_2: C32.2 R31.2 U2.1 | length 1705.9
  Layer 1 - Top Layer w10: v1(265,3535) R31.2@265,3568.5
  Layer 4 - Bottom Layer w10: v1(265,3535) 680,3535 800,3415 800,3030 873,2957 873,2633 837.17,2597.17 U2.1@612.4,2597.17
NetC33_1: C33.1 C35.2 R36.2 U2.5 | length 474.2
  Layer 1 - Top Layer w10: v1(281.5,2905) 281.5,2848.5 v1(350,2780)
  Layer 4 - Bottom Layer w10: v1(281.5,2905) R36.2@281.5,2945 ; v1(350,2780) 405,2780 446.5,2738.5 C35.2@475,2738.5 C33.1@475,2661.5 ; C35.2@475,2742.83 U2.5@536.61,2742.83
NetC34_2: C34.2 C36.1
NetC35_1: C35.1 C39.2 R37.2 U2.6 | length 342
  Layer 4 - Bottom Layer w10: R37.2@281.5,2805 286.5,2810 466.5,2810 C35.1@475,2801.5 476.5,2800 C39.2@543.5,2800 562.2,2781.3 U2.6@562.2,2734
NetC37_1: C37.1 C38.2
NetC40_1: C40.1 C43.2 R49.2 U3.4 | length 1146.6
  Layer 4 - Bottom Layer w10: R49.2@281.5,2535 281.5,2486.5 260,2465 110,2465 75,2430 75,2110 106.5,2078.5 C43.2@475,2078.5 ; C43.2@475,2077.17 U3.4@536.61,2077.17 ; C40.1@518.5,2020 536.61,2038.11 U3.4@536.61,2077.17 ; U3.4@536.61,2086 U3.4@536.61,2077.17
NetC40_2: C40.2 R47.2 U3.2 U3.3 | length 1471.5
  Layer 4 - Bottom Layer w10: R47.2@281.5,2670 281.5,2621.5 260,2600 110,2600 50,2540 50,2095 90,2055 320,2055 405,1970 565,1970 581.5,1986.5 C40.2@581.5,2020 562.2,2039.29 U3.3@562.2,2077.17 ; U3.3@563,2077.17 U3.2@587,2077.17
NetC41_2: C41.2 R41.2 U3.1 | length 128.2
  Layer 4 - Bottom Layer w10: U3.1@612.4,2077.17 R41.2@740.57,2077.17
NetC42_2: C42.2 C45.1
NetC43_1: C43.1 C44.2 R53.2 U3.5 | length 371.9
  Layer 1 - Top Layer w10: v1(300,2220) v1(435,2220)
  Layer 4 - Bottom Layer w10: R53.2@281.5,2270 281.5,2238.5 v1(300,2220) ; v1(435,2220) 473.5,2220 C44.2@475,2218.5 C43.1@475,2141.5 ; C44.2@475,2222.83 U3.5@536.61,2222.83
NetC44_1: C44.1 C46.2 R54.2 U3.6 | length 397.1
  Layer 4 - Bottom Layer w10: R54.2@281.5,2135 427.99,2281.5 C44.1@475,2281.5 476.5,2280 C46.2@543.5,2280 562.2,2261.3 U3.6@562.2,2214
NetC47_2: C47.2 D8.1 D13.3 Q12.4 R44.2 R59.1 R60.2 R66.2 R80.2 TP29.1 | length 2585.5
  Layer 1 - Top Layer w20: Q12.4@664.5,3445 v1(664.5,3475) ; v1(725,2555) 725,2651.5 R59.1@728.5,2655 R66.2@728.5,2710 C47.2@728.5,2765 735,2771.5 735,2829.47 D8.1@740.53,2835 745,2839.47 TP29.1@745,2930
  Layer 4 - Bottom Layer w20: v1(664.5,3475) 745,3394.5 TP29.1@745,2930 796.5,2930 R44.2@820,2906.5 ; v1(725,2555) R60.2@725,2451.5 863.5,2451.5 900,2415 900,1385 867.4,1352.4 D13.3@728,1352.4
NetC48_1: C48.1 C50.2 R72.2 U4.4 | length 1290.7
  Layer 4 - Bottom Layer w10: R72.2@281.5,1860 281.5,1811.5 260,1790 110,1790 75,1755 75,1430 100,1405 490,1405 518.5,1433.5 C48.1@518.5,1520 536.61,1538.11 U4.4@536.61,1577.17 ; C50.2@475,1577.17 U4.4@536.61,1577.17 ; U4.4@536.61,1586 U4.4@536.61,1577.17
NetC48_2: C48.2 R69.2 U4.2 U4.3 | length 1511.7
  Layer 4 - Bottom Layer w10: R69.2@281.5,1995 281.5,1946.5 260,1925 110,1925 50,1865 50,1415 85,1380 535,1380 581.5,1426.5 C48.2@581.5,1520 562.2,1539.29 U4.3@562.2,1577.17 ; U4.3@563,1577.17 U4.2@587,1577.17
NetC49_2: C49.2 R67.2 U4.1 | length 128.2
  Layer 4 - Bottom Layer w10: U4.1@612.4,1577.17 R67.2@740.57,1577.17
NetC50_1: C50.1 C51.2 R75.2 U4.5 | length 332.7
  Layer 1 - Top Layer w10: v1(321.5,1720) v1(435,1720)
  Layer 4 - Bottom Layer w10: R75.2@281.5,1720 v1(321.5,1720) ; v1(435,1720) 473.5,1720 C51.2@475,1718.5 C50.1@475,1641.5 ; C51.2@475,1722.83 U4.5@536.61,1722.83
NetC51_1: C51.1 C52.2 R78.2 U4.6 | length 562.1
  Layer 4 - Bottom Layer w10: R78.2@281.5,1465 281.5,1626.5 436.5,1781.5 C51.1@475,1781.5 476.5,1780 C52.2@543.5,1780 562.2,1761.3 U4.6@562.2,1714
NetC53_1: C53.1 C55.2 R84.2 U5.4 | length 1193.1
  Layer 4 - Bottom Layer w10: R84.2@281.5,1190 281.5,1141.5 260,1120 110,1120 75,1085 75,890 105,860 465,860 520,915 520,1021.5 536.61,1038.11 U5.4@536.61,1077.17 ; C55.2@475,1077.17 U5.4@536.61,1077.17 ; U5.4@536.61,1086 U5.4@536.61,1077.17
NetC53_2: C53.2 R83.2 U5.2 U5.3 | length 1428.7
  Layer 4 - Bottom Layer w10: R83.2@281.5,1325 281.5,1276.5 260,1255 110,1255 50,1195 50,875 90,835 535,835 581.5,881.5 C53.2@581.5,1020 562.2,1039.29 U5.3@562.2,1077.17 ; U5.3@563,1077.17 U5.2@587,1077.17
NetC54_2: C54.2 R81.2 U5.1 | length 128.2
  Layer 4 - Bottom Layer w10: U5.1@612.4,1077.17 R81.2@740.57,1077.17
NetC55_1: C55.1 C56.2 R85.2 U5.5 | length 426.6
  Layer 1 - Top Layer w10: v1(281.5,1090) 411.5,1220 v1(435,1220)
  Layer 4 - Bottom Layer w10: R85.2@281.5,1050 v1(281.5,1090) ; v1(435,1220) 473.5,1220 C56.2@475,1218.5 C55.1@475,1141.5 ; C56.2@475,1222.83 U5.5@536.61,1222.83
NetC56_1: C56.1 C57.2 R86.2 U5.6 | length 617.1
  Layer 4 - Bottom Layer w10: R86.2@281.5,910 380,1008.5 380,1225 436.5,1281.5 C56.1@475,1281.5 476.5,1280 C57.2@543.5,1280 562.2,1261.3 U5.6@562.2,1214
NetC61_1: C61.1 U11.20 | length 83.3
  Layer 1 - Top Layer w8: C61.1@3926.38,1335 3935,1326.38 3935,1318.15 3957.99,1295.16 U11.20@3957.99,1264.76
NetC67_1: C67.1 U11.67 | length 129.1
  Layer 1 - Top Layer w10: v1(4330,950) 4348.9,931.1 U11.67@4409.76,931.1
  Layer 4 - Bottom Layer w10: v1(4330,950) 4366.38,950 C67.1@4370,946.38
NetC71_1: C71.1 Q1.2 Q1.4 R9.1 R10.1
NetD1_1: D1.1 R1.2 | length 80.8
  Layer 1 - Top Layer w20: R1.2@3065,1528.5 v1(3100,1528.5)
  Layer 4 - Bottom Layer w20: v1(3100,1528.5) 3142.97,1528.5 D1.1@3145,1530.53
NetD2_1: D2.1 R5.2 R6.2
NetD3_1: D3.1 R45.2 | length 118
  Layer 1 - Top Layer w20: D3.1@325,3563.5 325,3522.91 372.09,3475.83 R45.2@372.09,3465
